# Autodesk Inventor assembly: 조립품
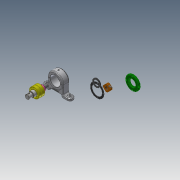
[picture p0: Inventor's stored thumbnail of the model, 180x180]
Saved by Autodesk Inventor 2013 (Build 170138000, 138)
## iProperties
Created: 2019-05
Part Number: 조립품
Document SubType Name: Assembly
Designer: 00
Author: 00
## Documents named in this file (13)
- C:\Users\00\Desktop\490504V1021\조립품.iam
- C:\Users\00\Desktop\490504V1021\본체.ipt
- C:\Users\00\Desktop\490504V1021\개스킷.ipt
- C:\Users\00\Desktop\490504V1021\그리스니플 M6.ipt
- 그리스니플  M6.ipt
- C:\Users\00\Desktop\490504V1021\그리스니플개스킷.ipt
- C:\Users\00\Desktop\490504V1021\베어링너트.ipt
- C:\Users\00\Desktop\490504V1021\볼트 M4.ipt
- C:\Users\00\Desktop\490504V1021\앵귤러 볼 베어링 7205.ipt
- C:\Users\00\Desktop\490504V1021\오일 실 28 40 5 B.ipt
- C:\Users\00\Desktop\490504V1021\축.ipt
- C:\Users\00\Desktop\490504V1021\칼라.ipt
- C:\Users\00\Desktop\490504V1021\커버.ipt
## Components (3 placed, 3 different names)
1. 개스킷:1
2. 그리스니플  M6:1
3. 그리스니플개스킷:1
